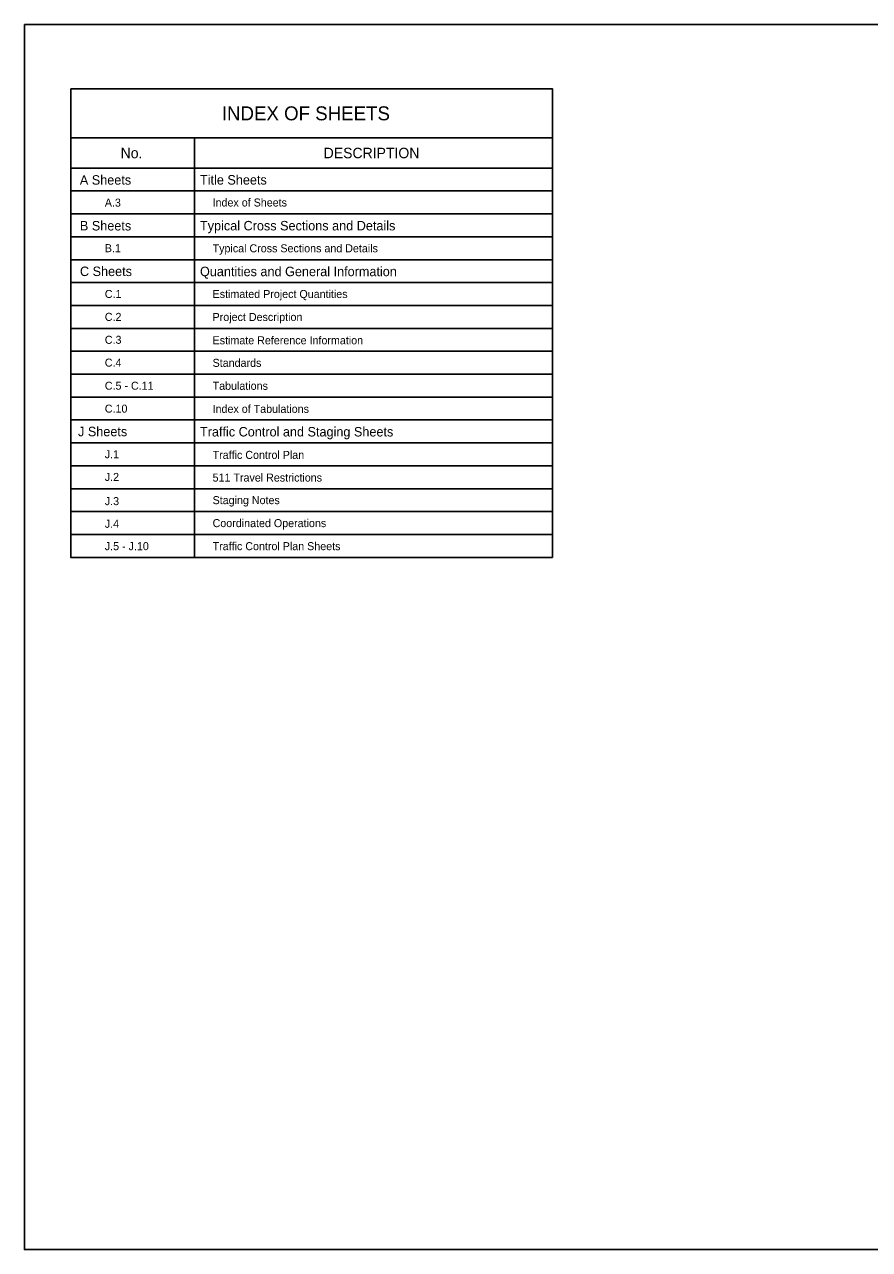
# Model space of a CAD drawing. Extents: x 10133 to 81668, y 7924 to 11018.
# Drawn here: x 10133 to 11526, y 7924 to 9944 of the extents above; entities that cross this region are included whole.
import ezdxf

# ---------------------------------------------------------------- set-up
doc = ezdxf.new("R2010")
doc.units = 0
doc.layers.add('SheetBorder', color=7, linetype='Continuous')

msp = doc.modelspace()

# ---------------------------------------------------------------- linework, layer by layer
at = {"layer": 'SheetBorder'}
for p, q in [((11003.2, 9757), (10208.8, 9757)), ((10412.8, 9757), (10412.8, 9065.3)), ((11003.2, 9707.3), (10208.8, 9707.3)), ((11003.2, 9669.5), (10208.8, 9669.5)), ((11003.2, 9631.8), (10208.8, 9631.8)), ((11003.2, 9594), (10208.8, 9594)), ((11003.2, 9556.2), (10208.8, 9556.2)), ((11003.2, 9518.5), (10208.8, 9518.5)), ((11003.2, 9480.7), (10208.8, 9480.7)), ((11003.2, 9442.9), (10208.8, 9442.9)), ((11003.2, 9405.2), (10208.8, 9405.2)), ((11003.2, 9367.4), (10208.8, 9367.4)), ((11003.2, 9329.6), (10208.8, 9329.6)), ((11003.2, 9291.9), (10208.8, 9291.9)), ((11003.2, 9254.1), (10208.8, 9254.1)), ((11003.2, 9216.4), (10208.8, 9216.4)), ((11003.2, 9178.6), (10208.8, 9178.6)), ((11003.2, 9140.8), (10208.8, 9140.8)), ((11003.2, 9103.1), (10208.8, 9103.1))]:
    msp.add_line(p, q, dxfattribs=at)
for points in [[(10132.5, 9944), (13267.5, 9944), (13267.5, 7924), (10132.5, 7924)], [(10208.8, 9838.1), (11003.2, 9838.1), (11003.2, 9065.3), (10208.8, 9065.3)]]:
    msp.add_lwpolyline(points, close=True, dxfattribs=at)

# ---------------------------------------------------------------- texts
for s, height, p in [('INDEX OF SHEETS', 23.04, (10458, 9786)), ('No.', 17.28, (10291.1, 9723.5)), ('DESCRIPTION', 17.28, (10626, 9723.5)), ('A Sheets', 15.6, (10223.8, 9679.9)), ('Title Sheets', 15.6, (10422, 9680.1)), ('A.3', 13.2, (10265, 9643.7)), ('Index of Sheets', 13.2, (10442.8, 9643.9)), ('B Sheets', 15.6, (10223.9, 9604.4)), ('Typical Cross Sections and Details', 15.6, (10422, 9604.5)), ('B.1', 13.2, (10265, 9568.6)), ('Typical Cross Sections and Details', 13.2, (10442.8, 9568.4)), ('C Sheets', 15.6, (10224, 9529.2)), ('Quantities and General Information', 15.6, (10422, 9529)), ('C.1', 13.2, (10265, 9493.1)), ('Estimated Project Quantities', 13.2, (10442.8, 9493)), ('C.2', 13.2, (10265, 9455.3)), ('Project Description', 13.2, (10442.8, 9455.1)), ('C.3', 13.2, (10265, 9417.5)), ('Estimate Reference Information', 13.2, (10442.8, 9416.7)), ('C.4', 13.2, (10265, 9379.9)), ('Standards', 13.2, (10442.8, 9379.5)), ('C.5 - C.11', 13.2, (10265, 9341.8)), ('Tabulations', 13.2, (10442.8, 9341.6)), ('C.10', 13.2, (10265, 9304)), ('Index of Tabulations', 13.2, (10442.8, 9303.6)), ('J Sheets', 15.6, (10220.8, 9265)), ('Traffic Control and Staging Sheets', 15.6, (10422, 9264.7)), ('J.1', 13.2, (10265, 9228.8)), ('Traffic Control Plan', 13.2, (10442.8, 9227.7)), ('J.2', 13.2, (10265, 9191.4)), ('511 Travel Restrictions', 13.2, (10442.8, 9190.3)), ('J.3', 13.2, (10265, 9151.5)), ('Staging Notes', 13.2, (10442.8, 9153.1)), ('J.4', 13.2, (10265, 9114.1)), ('Coordinated Operations', 13.2, (10442.8, 9115.2)), ('J.5 - J.10', 13.2, (10265, 9077.2)), ('Traffic Control Plan Sheets', 13.2, (10442.8, 9077.2))]:
    msp.add_text(s, height=height, dxfattribs=at).set_placement(p)

doc.saveas('drawing.dxf')
